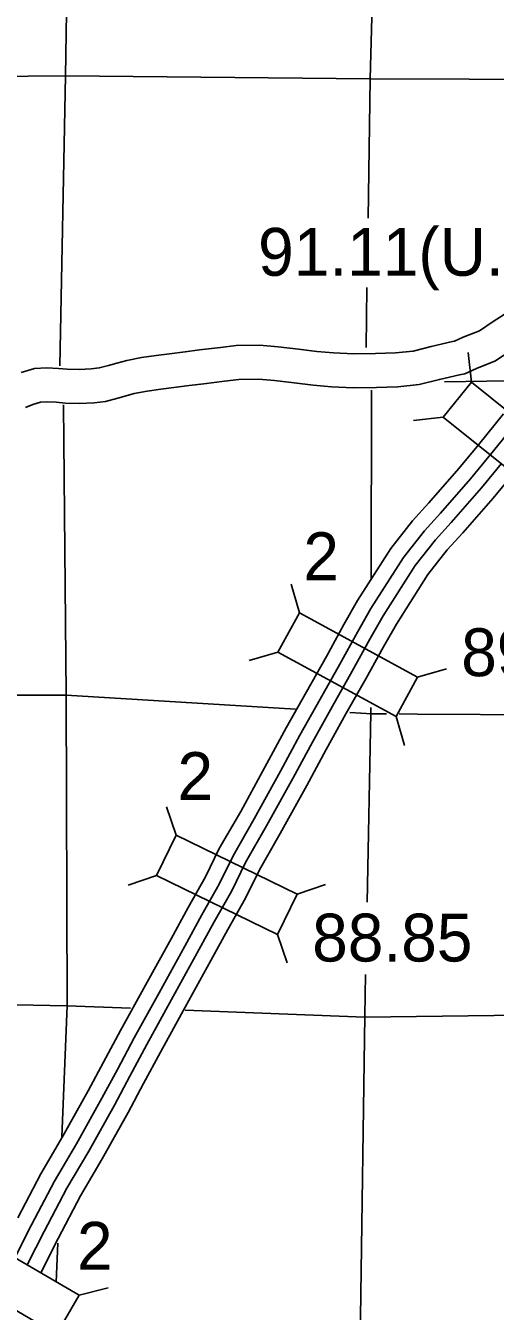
# Model space of a CAD drawing. Extents: x 369523 to 838377, y 495025 to 936819.
# Drawn here: x 618049 to 626332, y 838052 to 860745 of the extents above; entities that cross this region are included whole.
import ezdxf

# ---------------------------------------------------------------- set-up
doc = ezdxf.new("R2010")
doc.units = 0
for name, color, linetype in [('DSN_DRFT_Junk-No-Plot', 7, 'Continuous'), ('Level 1', 7, 'Continuous'), ('Level 15', 7, 'Continuous'), ('Level 21', 7, 'Continuous'), ('Level 22', 7, 'Continuous'), ('Level 23', 7, 'Continuous')]:
    doc.layers.add(name, color=color, linetype=linetype)

msp = doc.modelspace()

# ---------------------------------------------------------------- linework, layer by layer
at = {"layer": 'Level 1'}
for points in [[(625612, 855177), (625766, 855246), (626052, 855360), (626292, 855523), (626488, 855648), (626655, 855757), (626770, 855846), (626834, 855911)], [(625792, 854601), (626000, 854693), (626335, 854827), (626622, 855021), (626813, 855144), (627003, 855268), (627167, 855396), (627242, 855470)], [(625612, 855177), (625579, 855171), (625203, 855084), (624884, 855002), (624574, 854972), (624220, 854961), (623836, 854954), (623479, 854970), (623184, 854995), (622860, 855035), (622503, 855079), (622173, 855108), (621764, 855098), (621483, 855064), (621117, 855021), (620859, 854988), (620588, 854954), (620349, 854926), (620090, 854886), (619831, 854837), (619656, 854791), (619510, 854746), (619346, 854705), (619204, 854687), (618990, 854678), (618780, 854684), (618629, 854696), (618423, 854708), (618205, 854695), (617971, 854625)], [(625792, 854601), (625703, 854584), (625346, 854501), (624988, 854409), (624611, 854373), (624235, 854361), (623828, 854354), (623441, 854371), (623122, 854398), (622786, 854440), (622439, 854482), (622154, 854507), (621808, 854499), (621554, 854468), (621190, 854425), (620934, 854393), (620662, 854359), (620430, 854331), (620191, 854294), (619963, 854251), (619820, 854214), (619671, 854168), (619457, 854114), (619255, 854089), (618994, 854078), (618748, 854084), (618588, 854097), (618423, 854107), (618309, 854100), (618173, 854059), (618043, 854006)]]:
    msp.add_lwpolyline(points, dxfattribs=at)
at = {"layer": 'Level 15'}
msp.add_lwpolyline([(626930, 854480), (625438, 854461)], dxfattribs=at)
at = {"layer": 'Level 21'}
for p, q in [((625911, 854451), (625854, 854975)), ((625415, 853833), (624891, 853775)), ((622877, 850383), (622729, 850890)), ((622498, 849688), (621991, 849539)), ((624962, 849244), (625469, 849393)), ((624583, 848549), (624731, 848042)), ((620702, 846456), (620530, 846955)), ((620354, 845744), (619855, 845572)), ((622837, 845413), (623336, 845585)), ((622489, 844702), (622661, 844202)), ((618994, 838334), (619505, 838468))]:
    msp.add_line(p, q, dxfattribs=at)
for points in [[(625415, 853833), (627268, 852346), (627764, 852963), (625911, 854451)], [(624962, 849244), (622877, 850383), (622498, 849688), (624583, 848549)], [(622837, 845413), (620702, 846456), (620354, 845744), (622489, 844702)], [(618994, 838334), (616942, 839532), (616543, 838848), (618594, 837650)]]:
    msp.add_lwpolyline(points, close=True, dxfattribs=at)
at = {"layer": 'Level 22'}
for points in [[(619095, 875562), (618958, 870395), (618834, 865088), (618753, 859862), (618648, 854742)], [(624355, 875677), (624314, 870340), (624264, 865032), (624125, 859808), (624087, 857346)], [(629368, 859790), (624125, 859808), (618753, 859862), (613476, 859815), (608182, 859881)], [(624069, 856122), (624053, 855063)], [(624147, 854312), (624142, 850965)], [(618780, 843445), (618765, 848938), (618714, 854054)], [(608024, 848986), (613442, 848927), (618761, 848930), (622805, 848682)], [(623765, 848624), (624153, 848600), (624412, 848598)], [(624139, 848710), (624139, 848614), (624070, 845275)], [(624636, 848597), (624959, 848595)], [(624959, 848595), (629393, 848569), (632885, 848580)], [(624044, 843997), (624029, 843269), (623953, 837949), (623912, 835292)], [(618780, 843445), (613398, 843549), (607994, 843689)], [(618688, 841133), (618780, 843446)], [(619899, 843403), (618780, 843446)], [(628593, 843302), (624029, 843245), (620861, 843366)], [(618586, 838566), (618613, 839254)]]:
    msp.add_lwpolyline(points, dxfattribs=at)
at = {"layer": 'Level 23'}
for points in [[(626474, 853893), (626037, 853348), (625686, 852927), (625159, 852325), (624873, 852007), (624489, 851519), (623904, 850598), (623661, 850174), (623352, 849608), (623000, 848989), (622646, 848354), (622303, 847719), (621841, 846876), (621464, 846222), (621218, 845718), (620916, 845182), (620614, 844629), (620162, 843807), (619721, 843009), (619424, 842448), (619152, 841944), (618705, 841142), (618315, 840481), (617908, 839701)], [(626681, 853712), (626250, 853174), (625896, 852749), (625365, 852143), (625084, 851830), (624714, 851360), (624139, 850456), (623901, 850040), (623592, 849474), (623240, 848855), (622887, 848221), (622545, 847587), (622081, 846742), (621707, 846093), (621462, 845590), (621156, 845049), (620855, 844497), (620402, 843674), (619963, 842878), (619666, 842318), (619393, 841812), (618944, 841005), (618555, 840348), (618152, 839576), (617856, 838993)], [(626443, 853016), (626086, 852586), (625552, 851977), (625275, 851669), (624918, 851215), (624353, 850327), (624119, 849918), (623810, 849352), (623458, 848732), (623106, 848101), (622764, 847468), (622299, 846619), (621928, 845975), (621683, 845473), (621375, 844927), (621074, 844377), (620621, 843553), (620183, 842759), (619887, 842200), (619613, 841692), (619161, 840881), (618774, 840226), (618374, 839461), (618082, 838886)], [(626656, 852842), (626295, 852408), (625758, 851795), (625486, 851492), (625143, 851056), (624589, 850184), (624359, 849783), (624051, 849218), (623697, 848597), (623347, 847969), (623006, 847336), (622539, 846484), (622171, 845846), (621927, 845345), (621615, 844794), (621315, 844244), (620862, 843421), (620425, 842628), (620129, 842071), (619854, 841560), (619399, 840744), (619014, 840092), (618619, 839335), (618313, 838733)]]:
    msp.add_lwpolyline(points, dxfattribs=at)

# ---------------------------------------------------------------- texts
at = {"layer": 'DSN_DRFT_Junk-No-Plot'}
for s, p in [('91.11(U.P.)', (622148, 856331)), ('89.65', (625731, 849263)), ('88.85', (623102, 844226))]:
    msp.add_text(s, height=844.8, dxfattribs=at).set_placement(p)
at = {"layer": 'Level 21'}
for p in [(622946, 850957), (620726, 847077), (618953, 838785)]:
    msp.add_text('2', height=845, dxfattribs=at).set_placement(p)

doc.saveas('drawing.dxf')
